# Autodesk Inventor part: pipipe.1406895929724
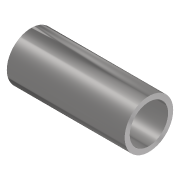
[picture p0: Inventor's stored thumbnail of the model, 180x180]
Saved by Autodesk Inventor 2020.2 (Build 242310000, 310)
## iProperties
Manager: www.cadconsulting.pl
Company: Fabian Stasiak CAD Consulting
IsCustomPart: 1
NAME: PIPING: JIS G 3458 Pipe
DATA: <meta><inlinegroups number="1" deflen="10"></inlinegroups><connections number="2"></connections><angles><a>3.14159265358979</a></angles></meta>
Created: 2014-08
Material: Stal, stopowa
Description: Rura
Document SubType Name: Modeling
Standard: JIS G 3458
Designer: F.Stasiak
Standards Organization: JIS
Language: pl-PL
Size Designation: 40 A x Sch 80 - 100
Categories: <MemberInstance><Categories><Category DisplayName="Rury cienko- i grubościenne" InternalName="4347fa0f-2144-441d-94cd-e3e15c92b736" Mnemonic="TUBEANDPIPE"><Cate
Stock Number: JIS G 3458 Rura 40 A x Sch 80
Density: 7.73 g/cm^3
Appearance: Częściowo polerowana
Catalog Web Link: www.expertbooks.pl
L: 118,000 mm
PL: 118,000 mm
Author: F.Stasiak
Subject: Zbiór ćwiczeń. Autodesk Inventor 2020. Kurs Professional
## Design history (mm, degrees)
sketch "Sketch1"
  geometry: C1 r 24.3 at (0, 0); C2 r 19.2 at (0, 0); 1 further point
  constraints: 2 centre point, 2 coincident, 1 concentric
  dimensions: "d0" = 48.6 diameter of C1 (= OD); "d1" = 38.4 diameter of C2 (= OD - 2 x t)
extrude "Extrusion1" new body sketch "Sketch1" distance "d2" = 118 (= L); taper "d3" = 0 deg
workaxis "Work Axis1"
workpoint "Work Point1"
workaxis "Work Axis2"
workpoint "Work Point2"
body "Solid1"
other parameters: "OD" = 48.6 [user parameter; used in 2 equation terms], "t" = 5.1 [user parameter; used in 1 equation term], "L" = 118 (= PL) [user parameter; used in 1 equation term], "ID" = 38.4 [user parameter], "PL" = 118 [user parameter; used in 1 equation term], "Size_Designation" = 12.345 [user parameter]
